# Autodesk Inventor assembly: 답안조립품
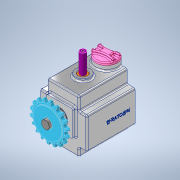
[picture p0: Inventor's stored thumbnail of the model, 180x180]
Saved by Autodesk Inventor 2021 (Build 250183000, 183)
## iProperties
Created: 2022-08
Part Number: 답안조립품
Document SubType Name: Assembly
Designer: Owner
Author: Owner
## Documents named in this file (16)
- C:\Users\Owner\Desktop\720810V1021\답안조립품.iam
- C:\Users\Owner\Desktop\720810V1021\본체.ipt
- C:\Users\Owner\Desktop\720810V1021\멈춤나사 M3.ipt
- C:\Users\Owner\Desktop\720810V1021\메인 축.ipt
- C:\Users\Owner\Desktop\720810V1021\베어링 608.ipt
- C:\Users\Owner\Desktop\720810V1021\베어링 6003.ipt
- C:\Users\Owner\Desktop\720810V1021\볼트 M4 x 10.ipt
- C:\Users\Owner\Desktop\720810V1021\부시.ipt
- C:\Users\Owner\Desktop\720810V1021\상부 캡.ipt
- C:\Users\Owner\Desktop\720810V1021\서브 축.ipt
- C:\Users\Owner\Desktop\720810V1021\스프로킷.ipt
- C:\Users\Owner\Desktop\720810V1021\슬라이더.ipt
- C:\Users\Owner\Desktop\720810V1021\오일 실 8 x 22 x 7.ipt
- C:\Users\Owner\Desktop\720810V1021\오일 실 17 x 32 x 8.ipt
- C:\Users\Owner\Desktop\720810V1021\커버.ipt
- C:\Users\Owner\Desktop\720810V1021\키 5 x 5.ipt
